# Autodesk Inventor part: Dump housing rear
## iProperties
Created: 2008-09
Part Number: Dump housing rear
Document SubType Name: Modeling
Designer: the-dude
Density: 1 g/cm^3
Author: the-dude
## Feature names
1. Partition outline [Revolution]
2. Output groove milling [Extrusion]
3. Output groove milling array [Circular Pattern]
4. Input groove milling 1 [Extrusion]
5. Input groove milling 2 [Fillet]
6. Input groove milling array [Circular Pattern]
7. Revolution4
